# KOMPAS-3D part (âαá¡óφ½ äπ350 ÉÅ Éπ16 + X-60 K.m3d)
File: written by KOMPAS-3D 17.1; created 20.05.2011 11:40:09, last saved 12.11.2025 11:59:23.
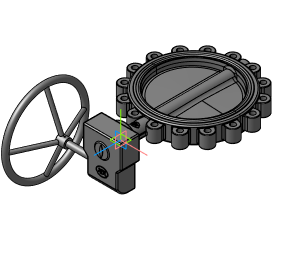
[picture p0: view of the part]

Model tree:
1. Плоскость XY
2. Плоскость ZX
3. Плоскость ZY
4. Ось X
5. Ось Y
6. Ось Z
7. Начало координат
8. Операция без истории:5

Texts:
  Viktor2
